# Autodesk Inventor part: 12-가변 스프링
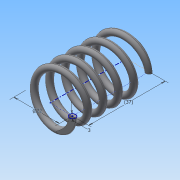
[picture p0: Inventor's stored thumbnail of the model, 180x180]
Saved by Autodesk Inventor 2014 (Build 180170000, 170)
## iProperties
Created: 2015-09
Part Number: 12-가변 스프링
Material: 강철, 탄소
Document SubType Name: Modeling
Designer: study
Density: 7.87 g/cm^3
Appearance: 반연마
Mass: 18.8856 g
Surface Area: 32.5491 cm^2
Volume: 2.3997 cm^3
Author: study
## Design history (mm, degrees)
sketch "스케치1"
  geometry: L1 (0, 0)-(11, 0); L2 (11, 0)-(11, 36.411); L3 (11, 36.411)-(0, 36.411); L4 (0, 36.411)-(0, 0); C1 r 1.5 at (11, 0)
  constraints: 8 end point, 2 parallel, 1 centre point, 1 coincident, 1 horizontal, 1 perpendicular
  dimensions: "d0" = 36.4112 distance of L1.end L2.end (derived); "d1" = 22 diameter of L2 L4; "d2" = 3 diameter of C1
feature "코일1" sketch "스케치1" pitch "d3" = 10; turns "d5" = 5; dims "d4" = 36.4112 (= d0), "d6" = 0, angle "d7" = 90 deg, angle "d8" = 90 deg, "d9" = 0, "d10" = 0
node "작업 평면1"
sketch "스케치2"
  geometry: L1 (-12.5, 0)-(-9.5, 0) reference; 1 further point
  constraints: 1 horizontal alignment
extrude "돌출1" cut sketch "스케치2" stored distance "d12" = 10; taper "d13" = 0 deg
node "작업 평면2"
sketch "스케치3"
  geometry: L1 (-9.5, 0)-(-12.5, 0) reference; 1 further point
  constraints: 1 horizontal alignment
extrude "돌출2" cut sketch "스케치3" stored distance "d15" = 10; taper "d16" = 0 deg
node "솔리드1"
node "절단 모서리 투영1"
node "절단 모서리 투영2"
other parameters: "d11" = 0, "d14" = 36.4112 (= d0)
